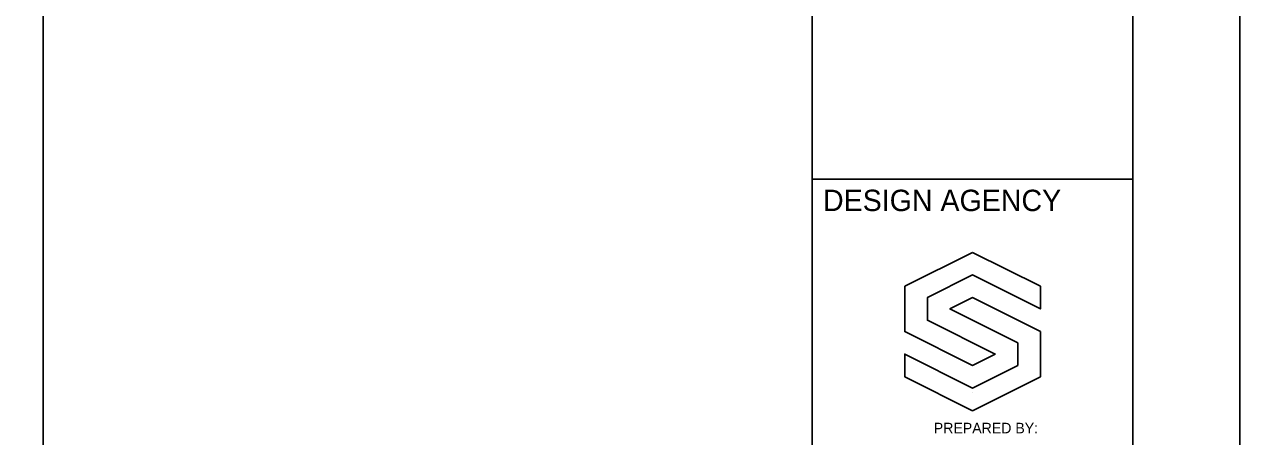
# Model space of a CAD drawing. Extents: x 0 to 34, y 0 to 22.
# Drawn here: x 28.31 to 34, y 3.79 to 5.72 of the extents above; entities that cross this region are included whole.
import ezdxf

# ---------------------------------------------------------------- set-up
doc = ezdxf.new("R2010")
doc.units = 0
for name, color, linetype in [('BORDER', 7, 'Continuous'), ('SH_Border', 7, 'Continuous'), ('SH_Cut_Line', 7, 'Continuous'), ('SH_Data', 7, 'Continuous')]:
    doc.layers.add(name, color=color, linetype=linetype)

msp = doc.modelspace()

# ---------------------------------------------------------------- linework, layer by layer
at = {"layer": 'BORDER'}
for p, q in [((32.75, 4.657), (32.4324, 4.4982)), ((33.0675, 4.4982), (32.75, 4.657)), ((32.5383, 4.4453), (32.75, 4.5511)), ((32.75, 4.5511), (33.0675, 4.3924)), ((32.4324, 4.4982), (32.4324, 4.2865)), ((33.0675, 4.3924), (33.0675, 4.4982)), ((32.5383, 4.3394), (32.5383, 4.4453)), ((32.75, 4.4453), (32.6441, 4.3924)), ((33.0675, 4.2865), (32.75, 4.4453)), ((32.6441, 4.3924), (32.9617, 4.2336)), ((32.8558, 4.1807), (32.5383, 4.3394)), ((32.4324, 4.2865), (32.75, 4.1277)), ((33.0675, 4.0748), (33.0675, 4.2865)), ((32.9617, 4.2336), (32.9617, 4.1277)), ((32.75, 4.0219), (32.4324, 4.1807)), ((32.4324, 4.1807), (32.4324, 4.0748)), ((32.75, 4.1277), (32.8558, 4.1807)), ((32.9617, 4.1277), (32.75, 4.0219)), ((32.4324, 4.0748), (32.75, 3.9161)), ((32.75, 3.9161), (33.0675, 4.0748))]:
    msp.add_line(p, q, dxfattribs=at)
for points in [[(32.75, 4.657), (32.4324, 4.4982), (32.4324, 4.2865), (32.75, 4.1277), (32.8558, 4.1807), (32.5383, 4.3394), (32.5383, 4.4453), (32.75, 4.5511), (33.0675, 4.3924), (33.0675, 4.4982), (32.75, 4.657)], [(32.75, 3.9161), (33.0675, 4.0748), (33.0675, 4.2865), (32.75, 4.4453), (32.6441, 4.3924), (32.9617, 4.2336), (32.9617, 4.1277), (32.75, 4.0219), (32.4324, 4.1807), (32.4324, 4.0748), (32.75, 3.9161)]]:
    msp.add_lwpolyline(points, dxfattribs=at)
at = {"layer": 'SH_Border'}
for p, q in [((32, 0.5), (32, 21.5)), ((32, 5), (33.5, 5))]:
    msp.add_line(p, q, dxfattribs=at)
msp.add_lwpolyline([(1.5, 21.5), (33.5, 21.5), (33.5, 0.5), (1.5, 0.5)], close=True, dxfattribs=at)
at = {"layer": 'SH_Cut_Line'}
msp.add_lwpolyline([(0, 0), (34, 0), (34, 22), (0, 22)], close=True, dxfattribs=at)
at = {"layer": 'SH_Data'}
msp.add_line((32.75, 4), (32.75, 4), dxfattribs=at)
msp.add_lwpolyline([(28.4, 7.85), (32, 7.85), (32, 3.75), (28.4, 3.75)], close=True, dxfattribs=at)

# ---------------------------------------------------------------- texts
at = {"layer": 'BORDER'}
msp.add_text('PREPARED BY:', height=0.049387, dxfattribs=at).set_placement((32.5685, 3.8102))
at = {"layer": 'SH_Data'}
msp.add_text('DESIGN AGENCY', height=0.1, dxfattribs=at).set_placement((32.05, 4.85))

doc.saveas('drawing.dxf')
